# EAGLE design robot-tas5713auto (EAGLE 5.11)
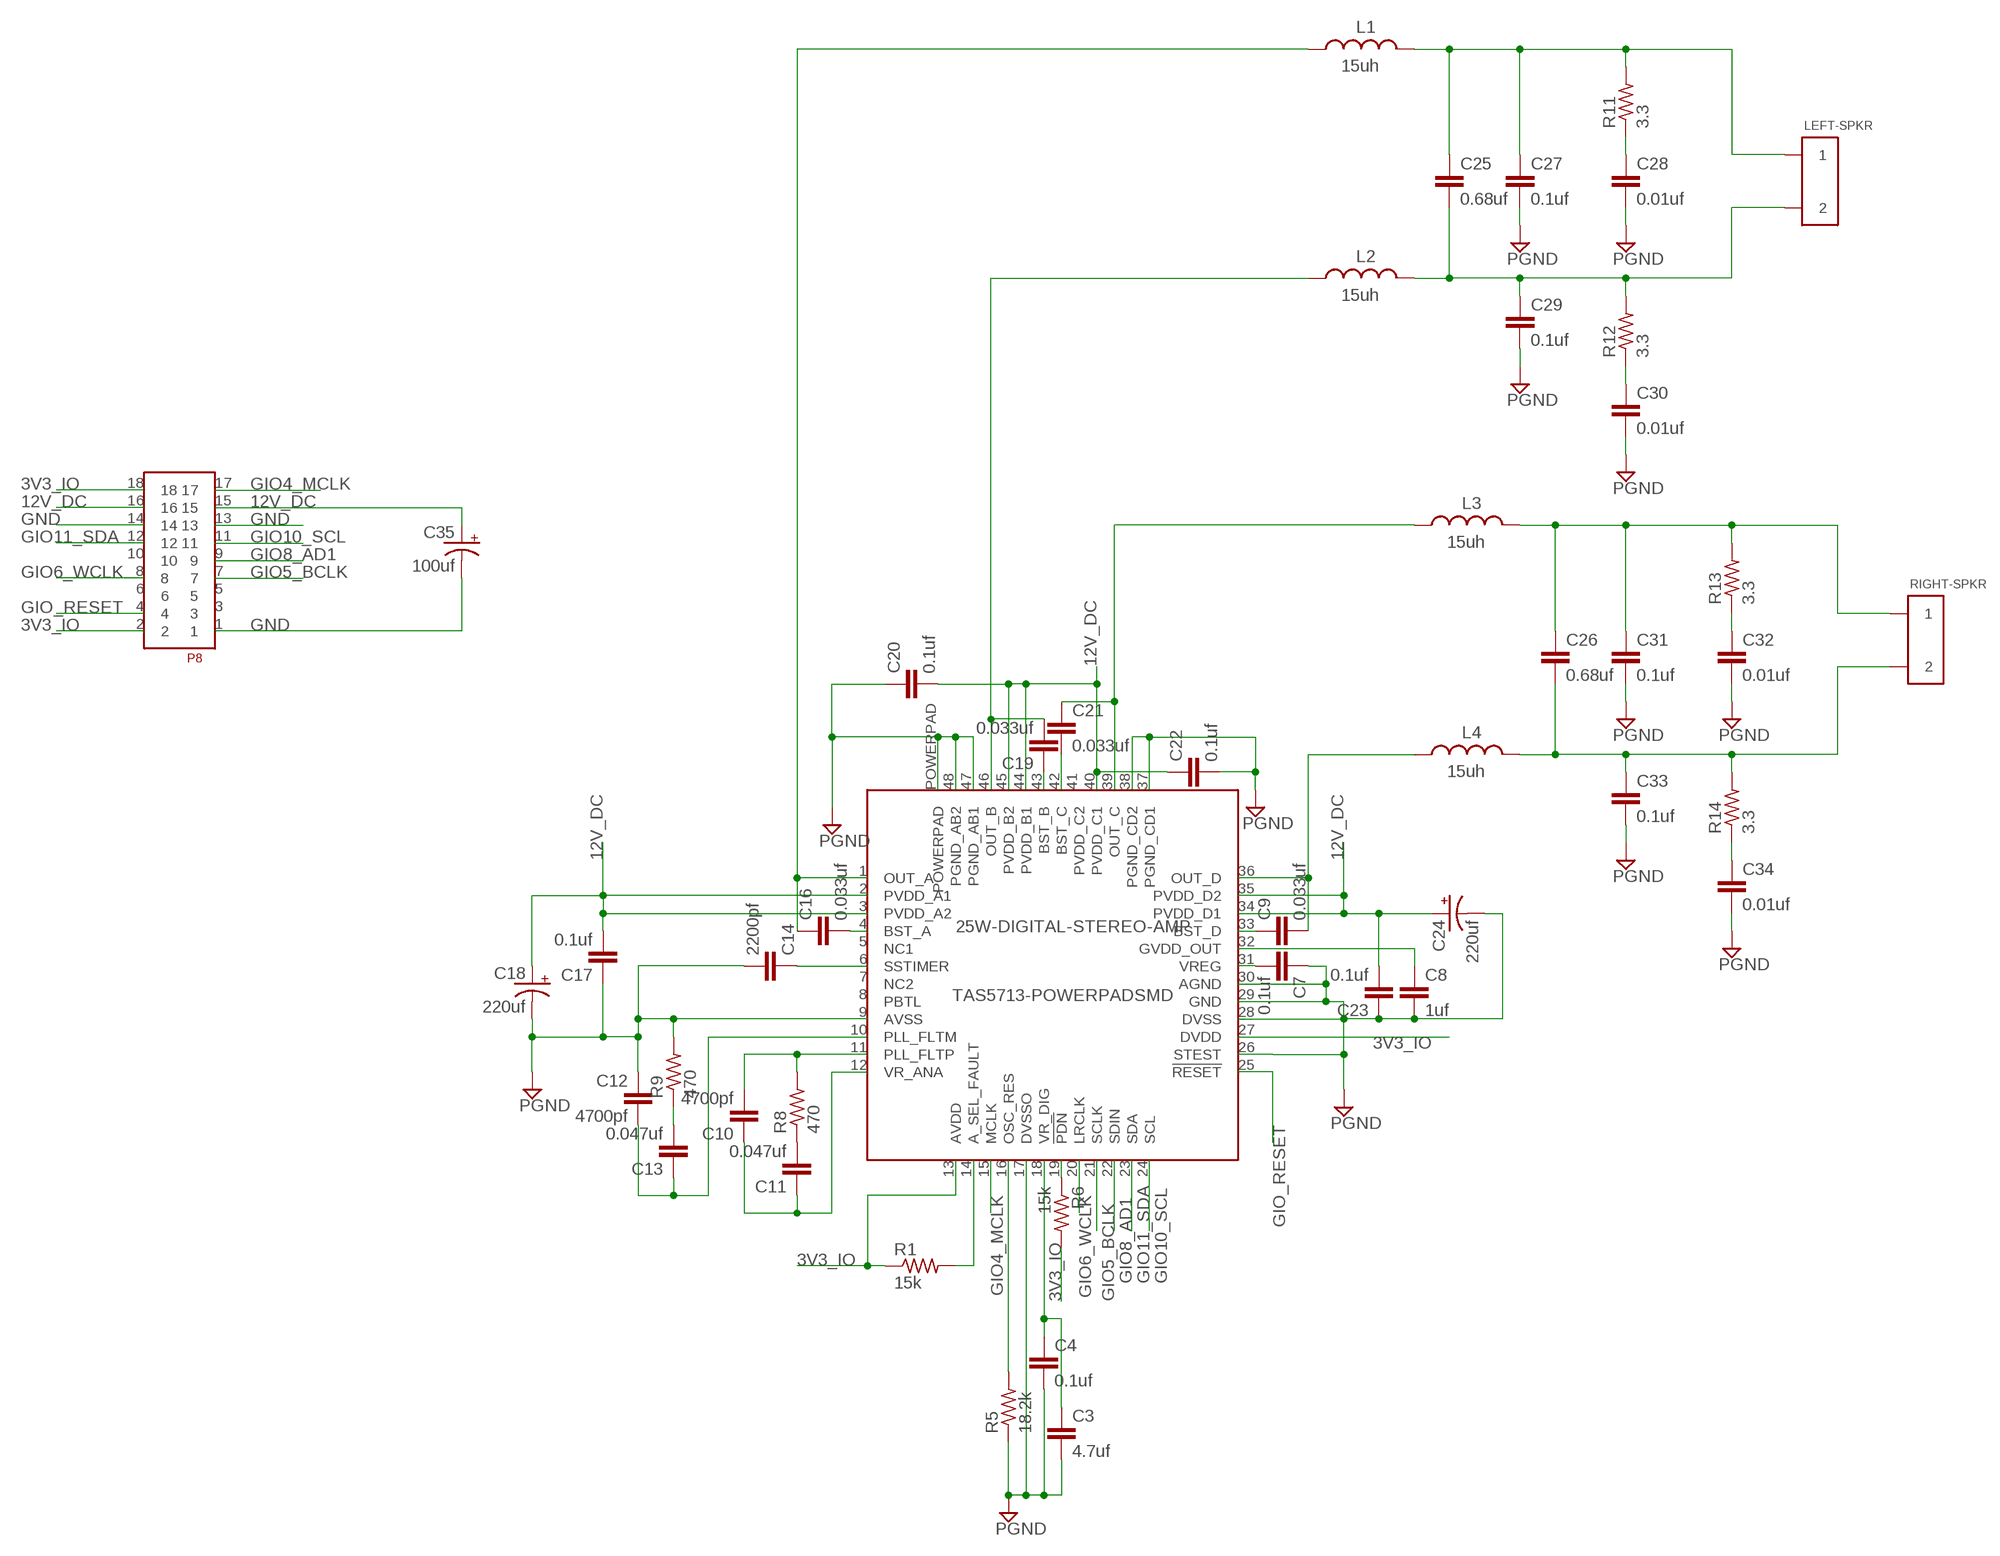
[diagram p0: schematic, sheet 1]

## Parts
25W-DIGITAL-STEREO-AMP  TAS5713-POWERPADSMD  [TQFP-48-POWERPAD]
C3  4.7uf  C-EUC1206  [C1206]
C4  0.1uf  C-EUC1206  [C1206]
C7  0.1uf  C-EUC1206  [C1206]
C8  1uf  C-EUC1206  [C1206]
C9  0.033uf  C-EUC1206  [C1206]
C10  4700pf  C-EUC1206  [C1206]
C11  0.047uf  C-EUC1206  [C1206]
C12  4700pf  C-EUC1206  [C1206]
C13  0.047uf  C-EUC1206  [C1206]
C14  2200pf  C-EUC1206  [C1206]
C16  0.033uf  C-EUC1206  [C1206]
C17  0.1uf  C-EUC1206  [C1206]
C18  220uf  CPOL-US175TMP-0808  [175TMP-0808]
C19  0.033uf  C-EUC1206  [C1206]
C20  0.1uf  C-EUC1206  [C1206]
C21  0.033uf  C-EUC1206  [C1206]
C22  0.1uf  C-EUC1206  [C1206]
C23  0.1uf  C-EUC1206  [C1206]
C24  220uf  CPOL-US175TMP-0808  [175TMP-0808]
C25  0.68uf  C-EUC1206  [C1206]
C26  0.68uf  C-EUC1206  [C1206]
C27  0.1uf  C-EUC1206  [C1206]
C28  0.01uf  C-EUC1206  [C1206]
C29  0.1uf  C-EUC1206  [C1206]
C30  0.01uf  C-EUC1206  [C1206]
C31  0.1uf  C-EUC1206  [C1206]
C32  0.01uf  C-EUC1206  [C1206]
C33  0.1uf  C-EUC1206  [C1206]
C34  0.01uf  C-EUC1206  [C1206]
C35  100uf  CPOL-US175TMP-0808  [175TMP-0808]
L1  15uh  INDUCTOR-ABRACON-1306S  [INDUCTOR-ABRACON-1306S]
L2  15uh  INDUCTOR-ABRACON-1306S  [INDUCTOR-ABRACON-1306S]
L3  15uh  INDUCTOR-ABRACON-1306S  [INDUCTOR-ABRACON-1306S]
L4  15uh  INDUCTOR-ABRACON-1306S  [INDUCTOR-ABRACON-1306S]
LEFT-SPKR  SCREW-CLAMP-2909  [SCREW-CLAMP-909]
P8  HEADER-2X9  [HEADER-2X9]
R1  15k  R-US_R1206  [R1206]
R5  18.2k  R-US_R1206  [R1206]
R6  15k  R-US_R1206  [R1206]
R8  470  R-US_R1206  [R1206]
R9  470  R-US_R1206  [R1206]
R11  3.3  R-US_R1206  [R1206]
R12  3.3  R-US_R1206  [R1206]
R13  3.3  R-US_R1206  [R1206]
R14  3.3  R-US_R1206  [R1206]
RIGHT-SPKR  SCREW-CLAMP-2909  [SCREW-CLAMP-909]

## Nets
3V3_IO: 25W-DIGITAL-STEREO-AMP.13(AVDD) 25W-DIGITAL-STEREO-AMP.27(DVDD) P8.2 P8.18 R1.1 R6.2
12V_DC: 25W-DIGITAL-STEREO-AMP.2(PVDD_A1) 25W-DIGITAL-STEREO-AMP.3(PVDD_A2) 25W-DIGITAL-STEREO-AMP.34(PVDD_D1) 25W-DIGITAL-STEREO-AMP.35(PVDD_D2) 25W-DIGITAL-STEREO-AMP.40(PVDD_C1) 25W-DIGITAL-STEREO-AMP.44(PVDD_B1) 25W-DIGITAL-STEREO-AMP.45(PVDD_B2) C17.2 C18.+ C20.2 C22.1 C23.2 C24.+ C35.+ P8.15 P8.16
GIO4_MCLK: 25W-DIGITAL-STEREO-AMP.15(MCLK) P8.17
GIO5_BCLK: 25W-DIGITAL-STEREO-AMP.21(SCLK) P8.7
GIO6_WCLK: 25W-DIGITAL-STEREO-AMP.20(LRCLK) P8.8
GIO8_AD1: 25W-DIGITAL-STEREO-AMP.22(SDIN) P8.9
GIO10_SCL: 25W-DIGITAL-STEREO-AMP.24(SCL) P8.11
GIO11_SDA: 25W-DIGITAL-STEREO-AMP.23(SDA) P8.12
GIO_RESET: 25W-DIGITAL-STEREO-AMP.25(!RESET) P8.4
GND: 25W-DIGITAL-STEREO-AMP.9(AVSS) 25W-DIGITAL-STEREO-AMP.17(DVSSO) 25W-DIGITAL-STEREO-AMP.26(STEST) 25W-DIGITAL-STEREO-AMP.28(DVSS) 25W-DIGITAL-STEREO-AMP.29(GND) 25W-DIGITAL-STEREO-AMP.30(AGND) 25W-DIGITAL-STEREO-AMP.37(PGND_CD1) 25W-DIGITAL-STEREO-AMP.38(PGND_CD2) 25W-DIGITAL-STEREO-AMP.47(PGND_AB1) 25W-DIGITAL-STEREO-AMP.48(PGND_AB2) 25W-DIGITAL-STEREO-AMP.POWERPAD C3.2 C4.2 C7.1 C8.2 C12.1 C14.2 C17.1 C18.- C20.1 C22.2 C23.1 C24.- C27.2 C28.2 C29.2 C30.2 C31.2 C32.2 C33.2 C34.2 C35.- P8.1 P8.13 P8.14 R5.1 R9.2 ; supply symbol labelled PGND
N$1: 25W-DIGITAL-STEREO-AMP.4(BST_A) C16.2
N$2: 25W-DIGITAL-STEREO-AMP.1(OUT_A) C16.1 L1.1
N$3: 25W-DIGITAL-STEREO-AMP.43(BST_B) C19.1
N$4: 25W-DIGITAL-STEREO-AMP.46(OUT_B) C19.2 L2.1
N$5: 25W-DIGITAL-STEREO-AMP.42(BST_C) C21.2
N$6: 25W-DIGITAL-STEREO-AMP.14(A_SEL_FAULT) R1.2
N$7: 25W-DIGITAL-STEREO-AMP.33(BST_D) C9.1
N$8: 25W-DIGITAL-STEREO-AMP.36(OUT_D) C9.2 L4.1
N$9: 25W-DIGITAL-STEREO-AMP.31(VREG) C7.2
N$10: 25W-DIGITAL-STEREO-AMP.32(GVDD_OUT) C8.1
N$11: 25W-DIGITAL-STEREO-AMP.6(SSTIMER) C14.1
N$12: C28.1 R11.1
N$13: C25.2 C29.1 L2.2 LEFT-SPKR.2 R12.2
N$14: C30.1 R12.1
N$15: 25W-DIGITAL-STEREO-AMP.39(OUT_C) C21.1 L3.1
N$16: 25W-DIGITAL-STEREO-AMP.18(VR_DIG) C3.1 C4.1
N$17: 25W-DIGITAL-STEREO-AMP.16(OSC_RES) R5.2
N$18: C26.1 C31.1 L3.2 R13.2 RIGHT-SPKR.1
N$19: C25.1 C27.1 L1.2 LEFT-SPKR.1 R11.2
N$20: C32.1 R13.1
N$21: C26.2 C33.1 L4.2 R14.2 RIGHT-SPKR.2
N$22: C34.1 R14.1
N$23: 25W-DIGITAL-STEREO-AMP.19(!PDN) R6.1
N$24: 25W-DIGITAL-STEREO-AMP.10(PLL_FLTM) C12.2 C13.1
N$25: 25W-DIGITAL-STEREO-AMP.11(PLL_FLTP) C10.2 R8.2
N$26: 25W-DIGITAL-STEREO-AMP.12(VR_ANA) C10.1 C11.1
N$27: C11.2 R8.1
N$28: C13.2 R9.1
Unconnected: 25W-DIGITAL-STEREO-AMP.5(NC1) 25W-DIGITAL-STEREO-AMP.7(NC2) 25W-DIGITAL-STEREO-AMP.8(PBTL) 25W-DIGITAL-STEREO-AMP.41(PVDD_C2) P8.3 P8.5 P8.6 P8.10

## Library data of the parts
25W-DIGITAL-STEREO-AMP = trl:TAS5713-POWERPAD
C3 C4 C7-C14 C16 C17 C19-C23 C25-C34 = rcl:C-EU: CAPACITOR, European symbol
C18 C24 C35 = resistor:CPOL-US: POLARIZED CAPACITOR, American symbol
L1-L4 = trl:INDUCTOR-ABRACON-1306S
LEFT-SPKR RIGHT-SPKR = trl:SCREW-CLAMP-2
P8 = trl:HEADER-2X9
R1 R5 R6 R8 R9 R11-R14 = resistor:R-US_: RESISTOR, American symbol

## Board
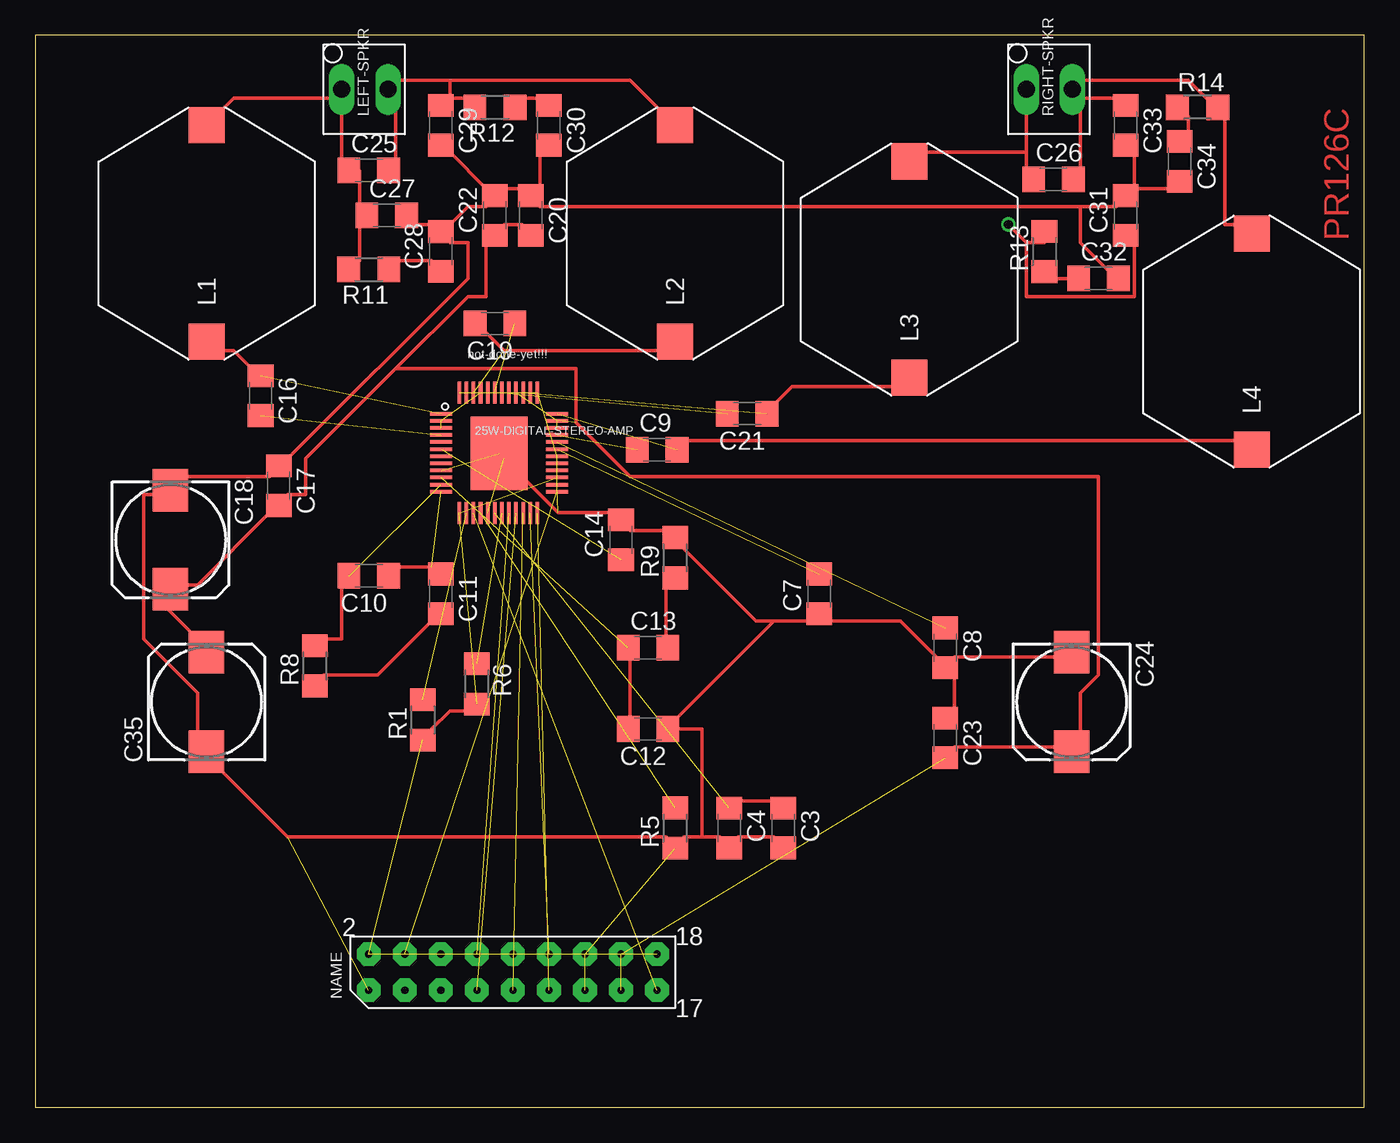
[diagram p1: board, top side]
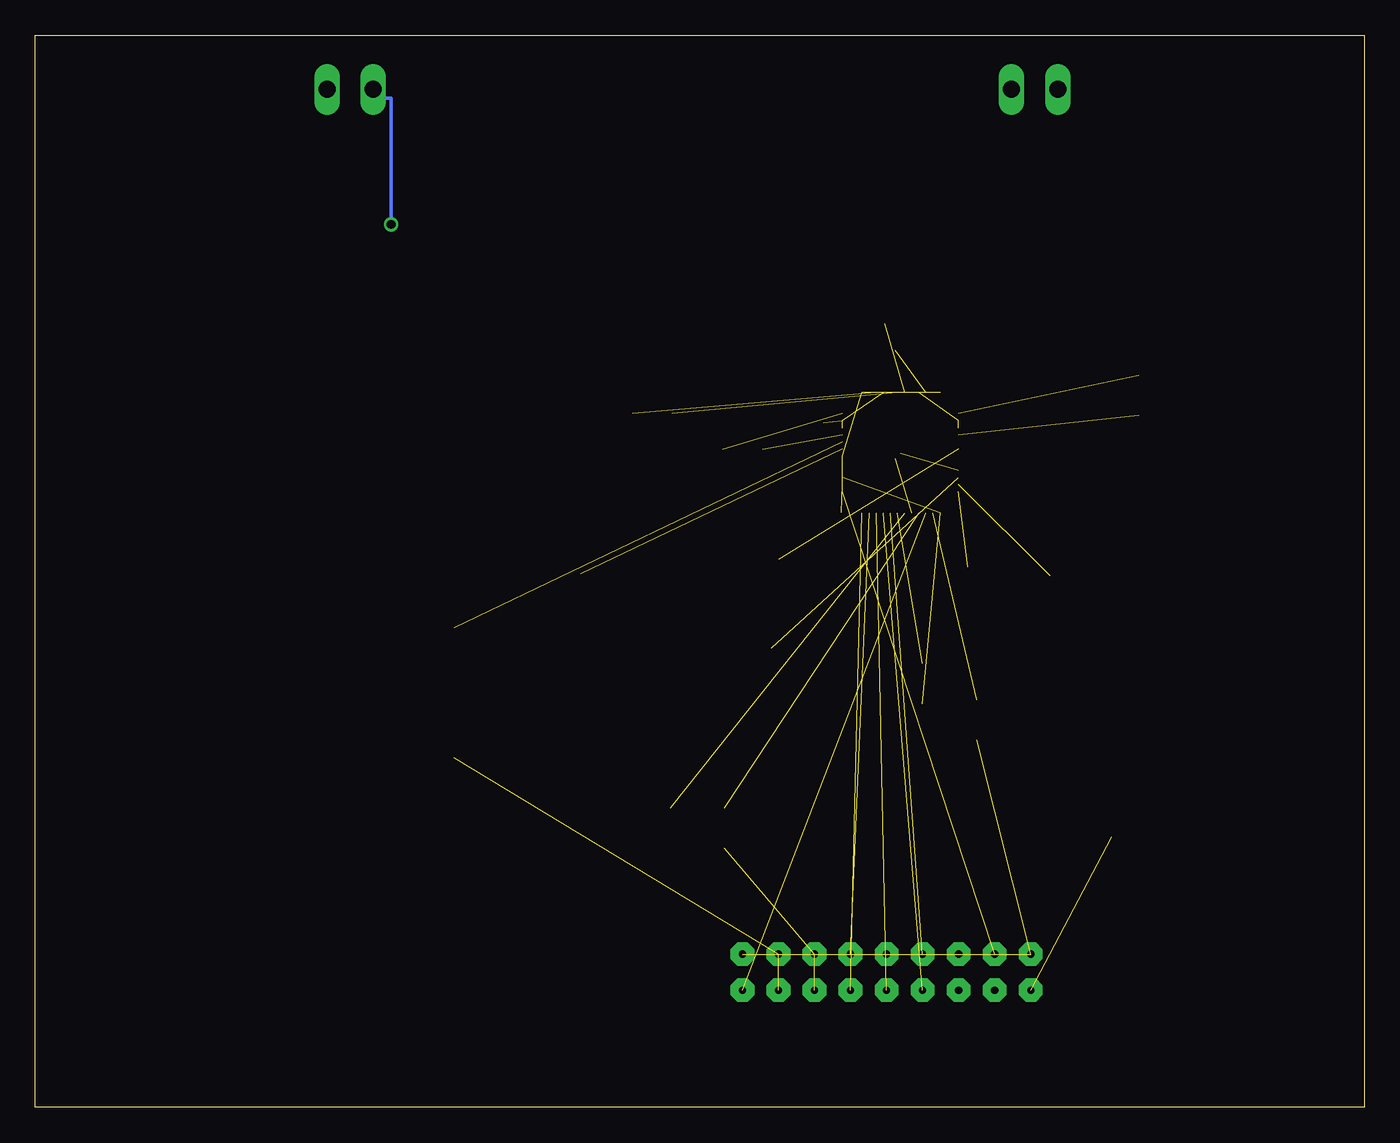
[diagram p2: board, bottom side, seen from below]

Size 93.65 x 75.56 mm. Coordinates in mm from the lower left corner, seen from the top.
Outline: 0,0 93.65,0 93.65,75.56 0,75.56 0,0
Copper layers (1*16): Top 0.035mm / dielectric 1.5mm / Bottom 0.035mm
Design rules "default": minimum track width 10mil, minimum drill 24mil, track to track 8mil, track to pad 8mil, pad to pad 8mil, via to via 8mil, smd to smd 8mil, copper to edge 40mil, drill to drill 8mil, minimum pad ring 10mil, minimum via ring 8mil, stop-mask expansion 4mil, vias tented up to drill 0mil, thermal gap 10mil

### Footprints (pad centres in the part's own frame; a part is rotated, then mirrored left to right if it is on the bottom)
TQFP-48-POWERPAD = smd 1.55 x 0.25: 1 -3.81,2.54; 2 -3.81,2.04; 3 -3.81,1.54; 4 -3.81,1.04; 5 -3.81,0.54; 6 -3.81,0.04; 7 -3.81,-0.46; 8 -3.81,-0.96; 9 -3.81,-1.46; 10 -3.81,-1.96; 11 -3.81,-2.46; 12 -3.81,-2.96; 25 4.39,-2.96; 26 4.39,-2.46; 27 4.39,-1.96; 28 4.39,-1.46; 29 4.39,-0.96; 30 4.39,-0.46; 31 4.39,0.04; 32 4.39,0.54; 33 4.39,1.04; 34 4.39,1.54; 35 4.39,2.04; 36 4.39,2.54 | smd 0.25 x 1.55: 13 -2.51,-4.46; 14 -2.01,-4.46; 15 -1.51,-4.46; 16 -1.01,-4.46; 17 -0.51,-4.46; 18 -0.01,-4.46; 19 0.49,-4.46; 20 0.99,-4.46; 21 1.49,-4.46; 22 1.99,-4.46; 23 2.49,-4.46; 24 2.99,-4.46; 37 2.99,4.04; 38 2.49,4.04; 39 1.99,4.04; 40 1.49,4.04; 41 0.99,4.04; 42 0.49,4.04; 43 -0.01,4.04; 44 -0.51,4.04; 45 -1.01,4.04; 46 -1.51,4.04; 47 -2.01,4.04; 48 -2.51,4.04 | smd 4.04 x 5.17: POWERPAD 0.29,-0.26
C1206 = smd 1.6 x 1.8: 1 -1.4,0; 2 1.4,0
175TMP-0808 = smd 3 x 2.5: + 3.5,0; - -3.5,0
INDUCTOR-ABRACON-1306S = smd 2.54 x 2.54: 1 0,0; 2 15.24,0
SCREW-CLAMP-909 = drill 1.2 long: 1 0,0; 2 3.251,0
HEADER-2X9 = drill 0.5 pad 1.676 octagon: 1 -11.43,-1.27; 2 -11.43,1.27; 3 -8.89,-1.27; 4 -8.89,1.27; 5 -6.35,-1.27; 6 -6.35,1.27; 7 -3.81,-1.27; 8 -3.81,1.27; 9 -1.27,-1.27; 10 -1.27,1.27; 11 1.27,-1.27; 12 1.27,1.27; 13 3.81,-1.27; 14 3.81,1.27; 15 6.35,-1.27; 16 6.35,1.27; 17 8.89,-1.27; 18 8.89,1.27
R1206 = smd 1.6 x 1.803: 1 -1.422,0; 2 1.422,0

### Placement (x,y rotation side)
25W-DIGITAL-STEREO-AMP  32.38,46.35 0 top
C3  52.7,19.68 270 top
C4  48.9,19.68 270 top
C7  55.24,36.2 90 top
C8  64.14,32.38 270 top
C9  43.81,46.35 0 top
C10  23.5,37.47 180 top
C11  28.57,36.2 270 top
C12  43.18,26.67 180 top
C13  43.18,32.38 0 top
C14  41.27,40.01 90 top
C16  15.88,50.16 270 top
C17  17.14,43.81 270 top
C18  9.53,40.01 270 top
C19  32.38,55.24 180 top
C20  34.92,62.87 270 top
C21  50.16,48.9 180 top
C22  32.38,62.87 90 top
C23  64.14,26.04 270 top
C24  73.03,28.57 270 top
C25  23.5,66.04 0 top
C26  71.75,65.41 0 top
C27  24.77,62.87 0 top
C28  28.57,60.33 90 top
C29  28.57,69.22 270 top
C30  36.2,69.22 270 top
C31  76.83,62.87 90 top
C32  74.93,58.42 0 top
C33  76.83,69.22 270 top
C34  80.64,66.67 270 top
C35  12.06,28.57 90 top
L1  12.06,53.98 90 top
L2  45.09,53.98 90 top
L3  61.59,51.44 90 top
L4  85.72,46.35 90 top
LEFT-SPKR  21.59,71.75 0 top
P8  34.92,9.53 0 top
R1  27.3,27.3 90 top
R5  45.09,19.68 90 top
R6  31.11,29.84 270 top
R8  19.68,31.11 90 top
R9  45.09,38.73 90 top
R11  23.5,59.05 180 top
R12  32.38,70.48 180 top
R13  71.12,60.33 90 top
R14  81.92,70.48 0 top
RIGHT-SPKR  69.85,71.75 0 top

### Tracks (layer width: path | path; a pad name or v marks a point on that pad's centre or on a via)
3V3_IO  (4 unrouted)
  Top 0.254: R1.1 27.94,26.67 29.21,27.94 30.48,27.94 R6.2
12V_DC  (9 unrouted)
  Top 0.254: C23.2 64.77,25.4 72.39,25.4 C24.+ 73.66,25.4 73.66,29.21 74.93,30.48 74.93,44.45 41.91,44.45 38.1,48.26 38.1,52.07 25.4,52.07 | C20.2 34.29,62.23 33.02,62.23 C22.1 31.75,60.96 31.75,57.15 30.48,57.15 25.4,52.07 | 25.4,52.07 19.05,45.72 19.05,43.18 17.78,43.18 C17.2 16.51,41.91 11.43,36.83 10.16,36.83 C18.+ 8.89,35.56 11.43,33.02 C35.+
GIO4_MCLK  (1 unrouted)
GIO5_BCLK  (1 unrouted)
GIO6_WCLK  (1 unrouted)
GIO8_AD1  (1 unrouted)
GIO10_SCL  (1 unrouted)
GIO11_SDA  (1 unrouted)
GIO_RESET  (1 unrouted)
GND  (13 unrouted)
  Top 0.254: C3.2 52.07,19.05 49.53,19.05 C4.2 48.26,19.05 46.99,19.05 | 46.99,19.05 45.72,19.05 R5.1 44.45,19.05 17.78,19.05 12.7,24.13 C35.- 11.43,25.4 11.43,29.21 7.62,33.02 7.62,43.18 8.89,43.18 C18.- 10.16,44.45 16.51,44.45 C17.1 17.78,45.72 30.48,58.42 30.48,60.96 29.21,60.96 C28.2 | C23.1 64.77,27.94 64.77,30.48 C8.2 | C8.2 64.77,31.75 72.39,31.75 C24.- | 52.07,34.29 44.45,26.67 C12.1 46.99,26.67 46.99,19.05 | 52.07,34.29 54.61,34.29 C7.1 55.88,34.29 60.96,34.29 63.5,31.75 C8.2 | 52.07,34.29 50.8,34.29 45.72,39.37 R9.2 44.45,40.64 41.91,40.64 C14.2 40.64,41.91 36.83,41.91 33.02,45.72 25W-DIGITAL-STEREO-AMP.POWERPAD | 73.66,63.5 73.66,60.96 76.2,58.42 C32.2 | 73.66,63.5 76.2,63.5 C31.2 77.47,64.77 | 77.47,64.77 80.01,64.77 C34.2 | 77.47,64.77 77.47,67.31 C33.2 | C27.2 26.67,62.23 27.94,62.23 C28.2 | C22.2 33.02,64.77 34.29,64.77 C20.1 | C29.2 29.21,67.31 31.75,64.77 C22.2 | C30.2 35.56,67.31 35.56,64.77 C20.1 | C28.2 29.21,62.23 30.48,63.5 31.75,63.5 C22.2 | 73.66,63.5 35.56,63.5 C20.1
N$1  (1 unrouted)
N$2  (1 unrouted)
  Top 0.254: C16.1 15.24,52.07 13.97,53.34 12.7,53.34 L1.1
N$3  (1 unrouted)
N$4  (1 unrouted)
  Top 0.254: C19.2 31.75,54.61 33.02,53.34 44.45,53.34 L2.1
N$5  (1 unrouted)
N$6  (1 unrouted)
N$7  (1 unrouted)
N$8  (1 unrouted)
  Top 0.254: C9.2 45.72,46.99 85.09,46.99 L4.1
N$9  (1 unrouted)
N$10  (1 unrouted)
N$11  (1 unrouted)
N$12
  Top 0.254: C28.1 27.94,59.69 25.4,59.69 R11.1
N$13
  Top 0.254: 29.21,71.12 30.48,71.12 R12.2 | C25.2 25.4,66.04 25.4,71.12 LEFT-SPKR.2 25.4,72.39 29.21,72.39 | 29.21,72.39 41.91,72.39 L2.2 | 29.21,72.39 29.21,71.12 | 29.21,71.12 C29.1
N$14
  Top 0.254: C30.1 35.56,71.12 34.29,71.12 R12.1
N$15  (1 unrouted)
  Top 0.254: C21.1 52.07,49.53 53.34,50.8 60.96,50.8 L3.1
N$16  (1 unrouted)
  Top 0.254: C4.1 49.53,21.59 52.07,21.59 C3.1
N$17  (1 unrouted)
N$18  (via drill 0.61)
  Top 0.254: 69.85,60.96 69.85,57.15 77.47,57.15 77.47,60.96 C31.1 | 69.85,60.96 71.12,60.96 R13.2 | 69.85,67.31 69.85,66.04 C26.1 | RIGHT-SPKR.1 69.85,67.31 | 69.85,67.31 62.23,67.31 L3.2 | 69.85,60.96 v68.58,62.23
  Bottom 0.254: v68.58,62.23 68.58,71.12 69.85,71.12 RIGHT-SPKR.1
N$19
  Top 0.254: R11.2 22.86,59.69 22.86,62.23 C27.1 22.86,63.5 22.86,66.04 C25.1 21.59,66.04 21.59,71.12 | 21.59,71.12 13.97,71.12 L1.2 | 21.59,71.12 LEFT-SPKR.1
N$20
  Top 0.254: 73.66,58.42 C32.1 71.12,58.42 R13.1
N$21
  Top 0.254: L4.2 85.09,62.23 83.82,62.23 83.82,69.85 R14.2 82.55,71.12 81.28,72.39 73.66,72.39 RIGHT-SPKR.2 73.66,71.12 | 73.66,71.12 73.66,66.04 C26.2 | 73.66,71.12 76.2,71.12 C33.1
N$22
  Top 0.254: C34.1 81.28,68.58 81.28,69.85 R14.1
N$23  (1 unrouted)
N$24  (1 unrouted)
  Top 0.254: C12.2 41.91,26.67 41.91,31.75 C13.1
N$25  (1 unrouted)
  Top 0.254: C10.2 21.59,36.83 21.59,33.02 20.32,33.02 R8.2
N$26  (1 unrouted)
  Top 0.254: C10.1 25.4,38.1 27.94,38.1 C11.1
N$27
  Top 0.254: C11.2 27.94,34.29 24.13,30.48 20.32,30.48 R8.1
N$28
  Top 0.254: C13.2 44.45,33.02 44.45,36.83 R9.1

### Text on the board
Top: PR126C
